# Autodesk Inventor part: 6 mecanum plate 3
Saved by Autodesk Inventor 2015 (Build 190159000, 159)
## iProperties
Created: 2015-01
Part Number: 6 mecanum plate 3
Material: Steel, Galvanized
Document SubType Name: Modeling
Designer: TODD D MILLER
Mass: 185.98 g
Surface Area: 388.601 cm^2
Volume: 23.6918 cm^3
Density: 7.85 g/cm^3
Appearance: Galvanized
Author: TODD D MILLER
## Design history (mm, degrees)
node "6 mecanum plate 3.ipt1"
node "Cut-Extrude1"
node "Base1"
